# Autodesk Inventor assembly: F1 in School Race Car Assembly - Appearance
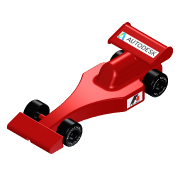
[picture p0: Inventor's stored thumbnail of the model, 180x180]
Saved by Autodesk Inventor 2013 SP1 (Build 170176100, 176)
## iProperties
Created: 2013-01
Part Number: F1 in School Race Car Assembly - Appearance
Document SubType Name: Assembly
Designer: banachd
Author: banachd
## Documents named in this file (5)
- C:\F1 in Schools\Workspace\Ex4 F1 Race Car Assembly - Appearance.iam
- C:\F1 in Schools\Workspace\Axle.ipt
- C:\F1 in Schools\Workspace\Retaining Ring.ipt
- C:\F1 in Schools\Workspace\Wheel.ipt
- C:\F1 in Schools\Workspace\Ex4 F1 Car Body Appearance Completed.ipt
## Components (9 placed, 4 different names)
1. Ex4 F1 Car Body Appearance Completed:1 — Mate:1, Mate:2, Insert:1, Insert:2, Insert:3
2. Axle:1 — Insert:4, Insert:6
3. Retaining Ring:1 — Insert:6
4. Axle:2 — Insert:5, Insert:7
5. Retaining Ring:2 — Insert:7
6. Wheel:1 — Insert:1, Insert:5
7. Wheel:2 — Insert:2
8. Wheel:3 — Mate:1, Mate:2, Insert:4
9. Wheel:4 — Insert:3
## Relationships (9: Insert 7, Mate 2)
- Mate:1: Ex4 F1 Car Body Appearance Completed:1 ↔ Wheel:3
- Mate:2: Ex4 F1 Car Body Appearance Completed:1 ↔ Wheel:3
- Insert:1: Ex4 F1 Car Body Appearance Completed:1 ↔ Wheel:1
- Insert:2: Ex4 F1 Car Body Appearance Completed:1 ↔ Wheel:2
- Insert:3: Ex4 F1 Car Body Appearance Completed:1 ↔ Wheel:4
- Insert:4: Axle:1 ↔ Wheel:3
- Insert:5: Axle:2 ↔ Wheel:1
- Insert:6: Axle:1 ↔ Retaining Ring:1
- Insert:7: Axle:2 ↔ Retaining Ring:2
